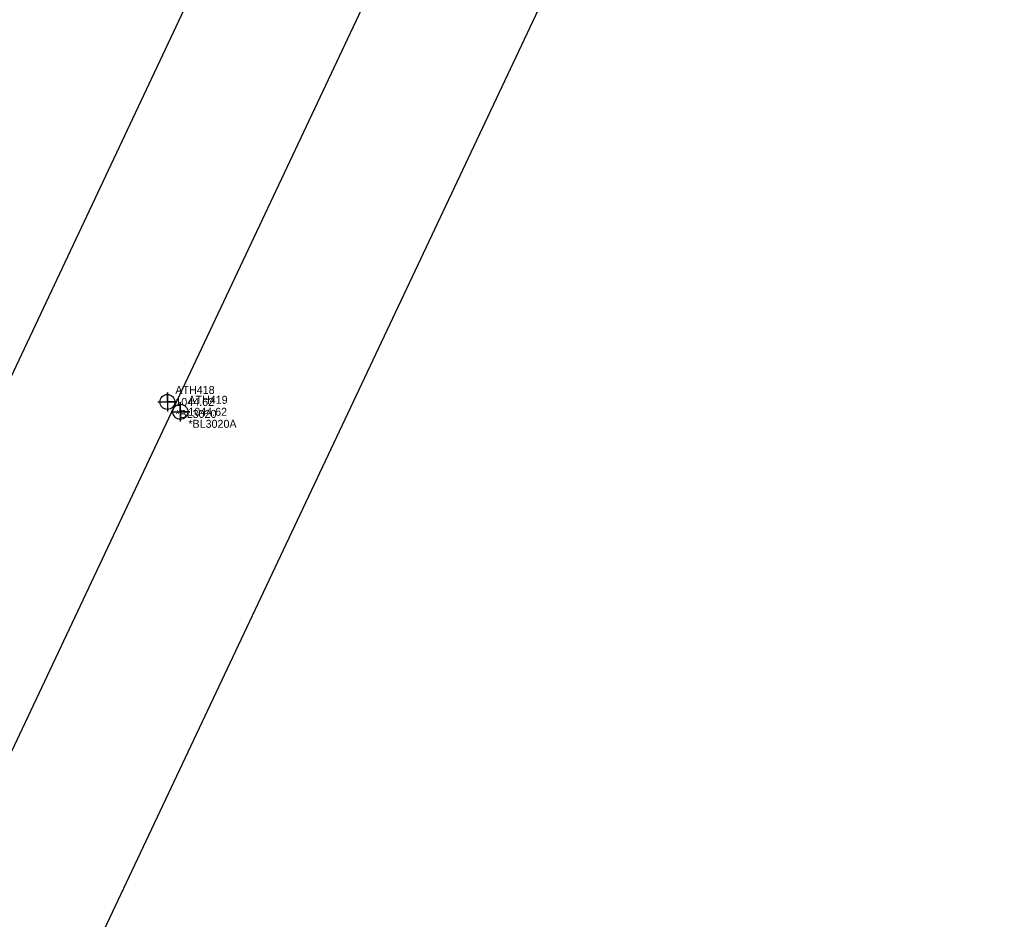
# Model space of a CAD drawing. Extents: x 1116345 to 1117546, y 660629 to 661859.
# Drawn here: x 1117234.8 to 1117545.5, y 661049.1 to 661330.1 of the extents above; entities that cross this region are included whole.
import ezdxf

# ---------------------------------------------------------------- set-up
doc = ezdxf.new("R2010")
doc.units = 0
for name, color, linetype in [('Exist Railroads Standard Gauge', 7, 'Continuous'), ('Exist Railroads Standard Gauge Cogo Comment', 7, 'Continuous'), ('Exist Railroads Standard Gauge Cogo Elevation', 7, 'Continuous'), ('Exist Railroads Standard Gauge Cogo Number', 7, 'Continuous'), ('Exist Railroads Standard Gauge Cogo Point CELL', 7, 'Continuous'), ('Exist Right of Way Line', 7, 'Continuous')]:
    doc.layers.add(name, color=color, linetype=linetype)

msp = doc.modelspace()

# ---------------------------------------------------------------- linework, layer by layer
at = {"layer": 'Exist Railroads Standard Gauge'}
msp.add_line((1117122.69, 660869.45), (1117501.06, 661671.99), dxfattribs=at)
at = {"layer": 'Exist Railroads Standard Gauge Cogo Point CELL'}
for points in [[(1117277.83, 661210.68), (1117283.83, 661210.68), (1117280.83, 661210.68), (1117280.83, 661213.68), (1117280.83, 661207.68)], [(1117281.88, 661207.6), (1117287.88, 661207.6), (1117284.88, 661207.6), (1117284.88, 661210.6), (1117284.88, 661204.6)]]:
    msp.add_lwpolyline(points, dxfattribs=at)
for centre in [(1117280.83, 661210.68), (1117284.88, 661207.6)]:
    msp.add_circle(centre, 2.34, dxfattribs=at)
at = {"layer": 'Exist Right of Way Line'}
for p, q in [((1117068.35, 660871.44), (1117455.09, 661691.74)), ((1117158.8, 660828.8), (1117545.54, 661649.09))]:
    msp.add_line(p, q, dxfattribs=at)

# ---------------------------------------------------------------- texts
at = {"layer": 'Exist Railroads Standard Gauge Cogo Comment'}
for s, p in [('*BL3020', (1117283.33, 661205.68)), ('*BL3020A', (1117287.38, 661202.6))]:
    msp.add_text(s, height=2.5, dxfattribs=at).set_placement(p)
at = {"layer": 'Exist Railroads Standard Gauge Cogo Elevation'}
for p in [(1117283.33, 661209.43), (1117287.38, 661206.35)]:
    msp.add_text('1044.62', height=2.5, dxfattribs=at).set_placement(p)
at = {"layer": 'Exist Railroads Standard Gauge Cogo Number'}
for s, p in [('ATH418', (1117283.33, 661213.18)), ('ATH419', (1117287.38, 661210.1))]:
    msp.add_text(s, height=2.5, dxfattribs=at).set_placement(p)

doc.saveas('drawing.dxf')
